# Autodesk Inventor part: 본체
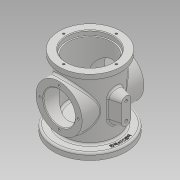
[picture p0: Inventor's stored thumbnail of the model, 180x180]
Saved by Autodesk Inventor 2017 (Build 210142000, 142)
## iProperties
Part Number: 본체
Material: 일반
Document SubType Name: Modeling
Designer: MRC
Density: 1 g/cm^3
Appearance: 기본값
Mass: 316.836 g
Surface Area: 757.291 cm^2
Volume: 316.836 cm^3
Author: MRC
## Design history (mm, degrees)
sketch "스케치2"
  geometry: C1 r 55 at (0, 0); 1 further point
  constraints: 1 centre point, 1 coincident
  dimensions: "d0" = 110 diameter of C1
extrude "돌출1" new body sketch "스케치2" distance "d1" = 10; taper "d2" = 0 deg
sketch "스케치3"
  geometry: C1 r 55 at (0, 0) reference; C2 r 40 at (0, 0)
  constraints: 1 centre point, 1 coincident
  dimensions: "d3" = 80 diameter of C2
extrude "돌출2" join sketch "스케치3" distance "d4" = 88; taper "d5" = 0 deg
sketch "스케치4"
  geometry: C1 r 40 at (0, 0) reference; C2 r 47 at (0, 0)
  constraints: 2 coincident, 1 centre point
  dimensions: "d6" = 94 diameter of C2
extrude "돌출3" join sketch "스케치4" distance "d7" = 10; taper "d8" = 0 deg
sketch "스케치9"
  geometry: L1 (-55, 0)-(55, 0) reference; C1 r 35 at (0, 54); 1 further point
  constraints: 1 centre point
  dimensions: "d21" = 70 diameter of C1; "d22" = 54 distance from line of L1 C1.centre
extrude "돌출8" join sketch "스케치9" stored distance "d23" = 94; taper "d24" = 0 deg
sketch "스케치5"
  geometry: C1 r 55 at (0, 0) reference; C2 r 33 at (0, 0)
  constraints: 1 centre point, 1 coincident
  dimensions: "d9" = 66 diameter of C2
extrude "돌출4" cut sketch "스케치5" distance "d10" = 16; taper "d11" = 0 deg
sketch "스케치6"
  geometry: C1 r 47 at (0, 0) reference; C2 r 33 at (0, 0)
  constraints: 1 centre point, 1 coincident
  dimensions: "d12" = 66 diameter of C2
extrude "돌출5" cut sketch "스케치6" distance "d13" = 86; taper "d14" = 0 deg
sketch "스케치7"
  geometry: C1 r 33 at (0, 0) reference; C2 r 47 at (0, 0) reference; C3 r 35 at (0, 0)
  constraints: 1 centre point, 1 coincident
  dimensions: "d15" = 70 diameter of C3
extrude "돌출6" cut sketch "스케치7" distance "d16" = 7; taper "d17" = 0 deg
sketch "스케치8"
  geometry: C1 r 33 at (0, 0) reference; C2 r 5 at (0, 0)
  constraints: 1 centre point, 1 coincident
  dimensions: "d18" = 10 diameter of C2
extrude "돌출7" cut sketch "스케치8" distance "d19" = 30; taper "d20" = 0 deg
sketch "스케치10"
  geometry: C1 r 35 at (0, 0) reference; C2 r 24 at (0, 0); 1 further point
  constraints: 1 centre point, 1 coincident
  dimensions: "d25" = 48 diameter of C2
extrude "돌출9" cut sketch "스케치10" distance "d26" = 94; taper "d27" = 0 deg
chamfer "모따기1" distance "d28" = 1; stored, may be unused: second distance "d29" = 2, angle "d30" = 45 deg
fillet "모깎기1" dims "d32" = 3
sketch "스케치11"
  geometry: C1 r 43 at (0, 0) reference; C2 r 50 at (0, 0)
  constraints: 1 centre point, 1 coincident, 1 other
  dimensions: "d33" = 100 diameter of C2
feature "엠보싱1" sketch "스케치11" dims "d11" = 0, "d34" = 0.5, "d35" = 0
sketch "스케치12" dims "d36" = 58
  geometry: C1 r 35 at (0, 0) reference; C2 r 25 at (0, 0) reference; 3 further points
  constraints: 2 vertical alignment, 1 coincident, 2 other
hole "구멍1" sketch "스케치12" at (0, 29) diameter "d37" = 3.242; stored, may be unused: countersink angle "d41" = 90 deg, drill point angle "d43" = 118 deg; dims "d38" = 6, "d39" = 4, "d40" = 6, "d42" = 8
sketch "스케치13" dims "d47" = 80
  geometry: C1 r 47 at (0, 0) reference; C2 r 36 at (0, 0) reference; 2 further points
  constraints: 2 horizontal alignment, 1 coincident, 2 other
hole "구멍2" sketch "스케치13" at (40, 0) diameter "d48" = 3.242; stored, may be unused: countersink angle "d52" = 90 deg, drill point angle "d54" = 118 deg; dims "d49" = 6, "d50" = 4, "d51" = 6, "d53" = 8
sketch "스케치14" dims "d58" = 58
  geometry: C1 r 35 at (0, 0) reference; C2 r 25 at (0, 0) reference; 3 further points
  constraints: 2 horizontal alignment, 1 coincident, 2 other
hole "구멍3" sketch "스케치14" at (-29, 0) diameter "d59" = 3.242; stored, may be unused: countersink angle "d63" = 90 deg, drill point angle "d65" = 118 deg; dims "d60" = 6, "d61" = 4, "d62" = 6, "d64" = 8
node "작업 평면1"
sketch "스케치15"
  geometry: L1 (0, 74)-(0, 34); L2 (-7, 67)-(-7, 41); L3 (7, 41)-(7, 67); L4 (-55, 0)-(55, 0) reference; A1 r 7 centre (0, 67) between (7, 67) and (-7, 67); A2 r 7 centre (0, 41) between (-7, 41) and (7, 41); 3 further points
  constraints: 8 end point, 6 point on circle, 4 tangent, 2 centre point, 2 midpoint, 2 point on line, 1 parallel, 1 vertical, 1 vertical alignment
  dimensions: "d69" = 54 distance from line of L4 point (0, 54); "d70" = 7 radius of A1; "d71" = 40 distance of L1.end L1.start
extrude "돌출10" join sketch "스케치15" stored distance "d72" = 94; taper "d73" = 15 deg
sketch "스케치16"
  geometry: A1 r 7 centre (-41, 0) between (-41, -7) and (-41, 7) reference; A2 r 7 centre (-67, 0) between (-67, 7) and (-67, -7) reference; 3 further points
  constraints: 2 coincident
hole "구멍4" sketch "스케치16" at (-41, 0), (-67, 0) diameter "d74" = 4.134; stored, may be unused: countersink angle "d78" = 90 deg, drill point angle "d80" = 118 deg; dims "d75" = 6, "d76" = 4, "d77" = 6, "d79" = 8
fillet "모깎기2" dims "d81" = 3
fillet "모깎기3" dims "d82" = 3
node "솔리드1"
pattern_circular "원형 패턴1" dims angle "d45" = 360 deg
pattern_circular "원형 패턴2" dims angle "d56" = 360 deg
pattern_circular "원형 패턴3" dims angle "d67" = 360 deg
other parameters: "d31" = 55
